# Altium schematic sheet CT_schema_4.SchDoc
size 229 x 200 mm
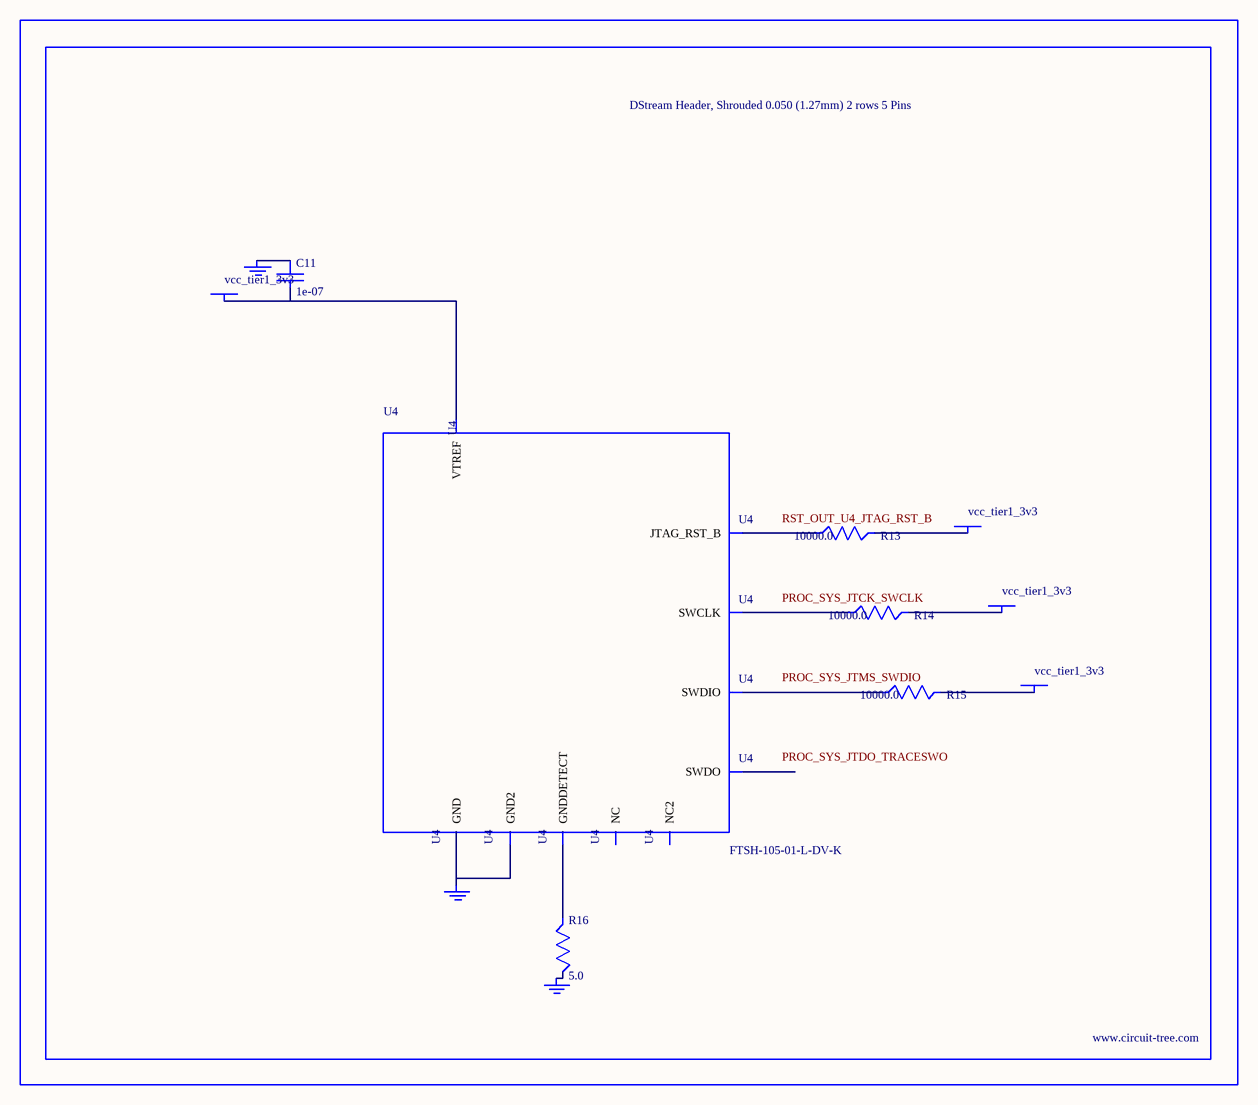
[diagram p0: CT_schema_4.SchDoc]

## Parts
BORDER3  (no value)
C11  1e-07  [C0402]
GND_INSTANCE_3_0  (no value)
GND_INSTANCE_3_1  (no value)
GND_INSTANCE_3_2  (no value)
POWER_INSTANCE_3_0  vcc_tier1_3v3
POWER_INSTANCE_3_1  vcc_tier1_3v3
POWER_INSTANCE_3_2  vcc_tier1_3v3
POWER_INSTANCE_3_3  vcc_tier1_3v3
R13  10000.0  [R0603]
R14  10000.0  [R0603]
R15  10000.0  [R0603]
R16  5.0  [R0603]
U4  FTSH-105-01-L-DV-K  [SAMTEC_FTSH-105-01-L-DV-K]

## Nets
NetC11_1: C11.1 GND_INSTANCE_3_0.0(GND)
NetC11_2: C11.2 POWER_INSTANCE_3_0.0(PWR) U4.1(VTREF)
NetGND_INSTANCE_3_1_0: GND_INSTANCE_3_1.0(GND) R16.2
NetGND_INSTANCE_3_2_0: GND_INSTANCE_3_2.0(GND) U4.3(GND) U4.5(GND2)
NetPOWER_INSTANCE_3_1_0: POWER_INSTANCE_3_1.0(PWR) R15.2
NetPOWER_INSTANCE_3_2_0: POWER_INSTANCE_3_2.0(PWR) R14.2
NetPOWER_INSTANCE_3_3_0: POWER_INSTANCE_3_3.0(PWR) R13.2
NetR13_1: R13.1 U4.10(JTAG_RST_B)
NetR14_1: R14.1 U4.4(SWCLK)
NetR15_1: R15.1 U4.2(SWDIO)
NetR16_1: R16.1 U4.9(GNDDETECT)

Not connected (* = marked no-connect by the designer): U4 6(SWDO) 7(NC) 8(NC2)

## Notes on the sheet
- Labels drawn without touching a wire or pin: PROC_SYS_JTCK_SWCLK, PROC_SYS_JTDO_TRACESWO, PROC_SYS_JTMS_SWDIO, RST_OUT_U4_JTAG_RST_B

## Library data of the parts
BORDER3 = BORDER_PAGE3
C11 = C0402C104K3RACTU
GND_INSTANCE_3_0-GND_INSTANCE_3_2 = GND
POWER_INSTANCE_3_0-POWER_INSTANCE_3_3 = PWR
R13-R15 = RC0603JR-0710KL
R16 = ERJ-3GEYJ5R1V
